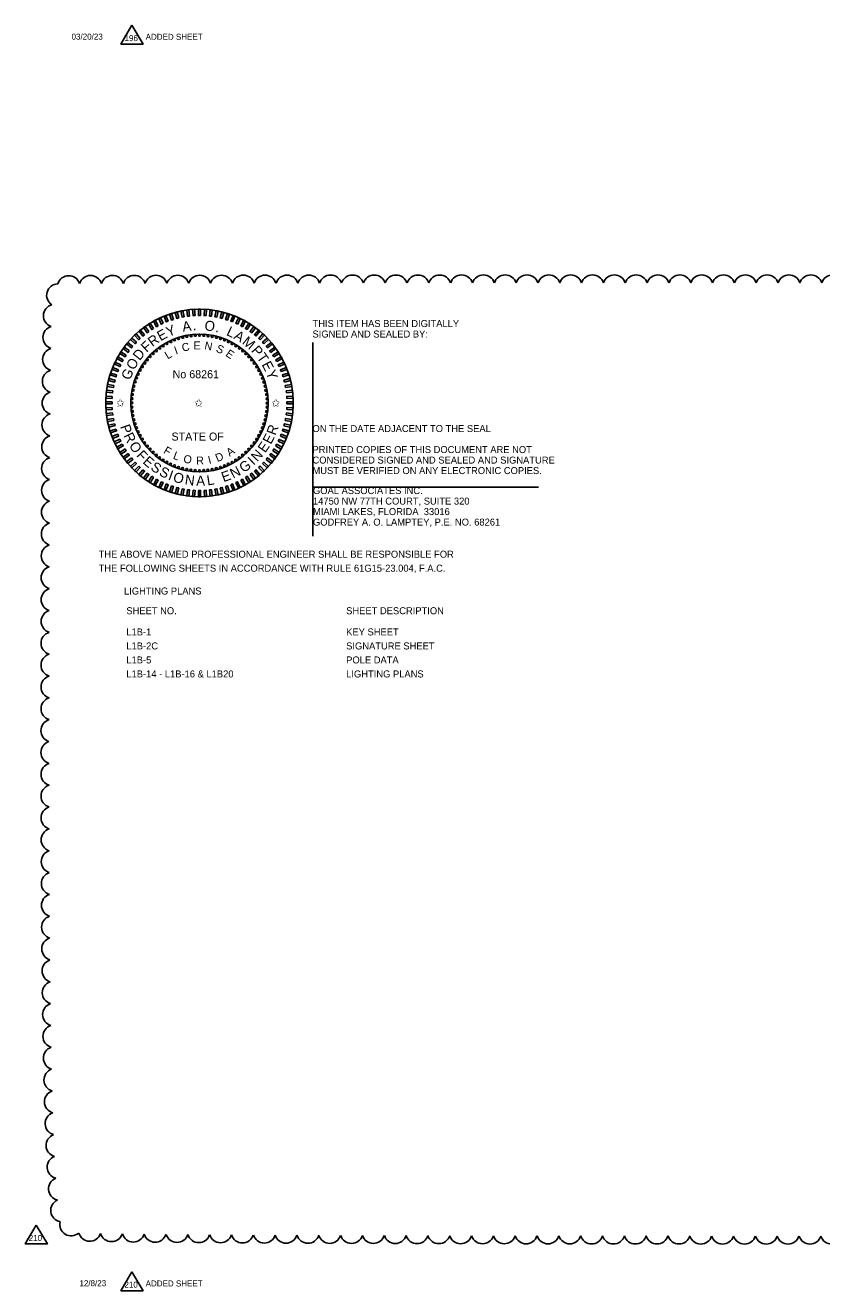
# Model space of a CAD drawing. Extents: x -811.2 to -755.6, y -2295.2 to -2235.1.
# Drawn here: x -811.23 to -803.27, y -2282.51 to -2269.86 of the extents above; entities that cross this region are included whole.
import ezdxf

# ---------------------------------------------------------------- set-up
doc = ezdxf.new("R2010")
doc.units = 0
for name, color, linetype in [('Cloud_dp', 7, 'Continuous'), ('Logo_dp', 7, 'Continuous'), ('NonPlottingEle_dp', 7, 'Continuous'), ('ScratchEle_dp', 7, 'Continuous'), ('TextMinor', 7, 'Continuous'), ('TextMisc', 7, 'Continuous'), ('TextNotes', 7, 'Continuous')]:
    doc.layers.add(name, color=color, linetype=linetype)

msp = doc.modelspace()

# ---------------------------------------------------------------- linework, layer by layer
at = {"layer": 'Cloud_dp'}
for points in [[(-810.168, -2269.863), (-810.276, -2270.051), (-810.055, -2270.051)], [(-811.125, -2281.857), (-811.233, -2282.045), (-811.012, -2282.045)], [(-810.168, -2282.324), (-810.276, -2282.512), (-810.055, -2282.512)]]:
    msp.add_lwpolyline(points, close=True, dxfattribs=at)
for centre, start, end in [((-810.798, -2272.48), 18.0566, 163.0566), ((-810.58, -2272.478), 17.7998, 162.7998), ((-810.362, -2272.477), 17.7187, 162.7187), ((-810.143, -2272.477), 17.6743, 162.6743), ((-809.925, -2272.476), 17.6451, 162.6451), ((-809.707, -2272.476), 17.624, 162.624), ((-809.488, -2272.475), 17.6079, 162.6079), ((-809.27, -2272.475), 17.5951, 162.5951), ((-809.052, -2272.474), 17.5845, 162.5845), ((-808.834, -2272.474), 17.5756, 162.5756), ((-808.615, -2272.474), 17.568, 162.568), ((-808.397, -2272.474), 17.5614, 162.5614), ((-808.179, -2272.473), 17.5556, 162.5556), ((-807.96, -2272.473), 17.5505, 162.5505), ((-807.742, -2272.473), 17.5459, 162.5459), ((-807.524, -2272.473), 17.5417, 162.5417), ((-807.305, -2272.473), 17.5379, 162.5379), ((-807.087, -2272.473), 17.5344, 162.5344), ((-806.869, -2272.472), 17.5313, 162.5313), ((-806.65, -2272.472), 17.5283, 162.5283), ((-806.432, -2272.472), 17.5256, 162.5256), ((-806.214, -2272.472), 17.5231, 162.5231), ((-805.995, -2272.472), 17.5207, 162.5207), ((-805.777, -2272.472), 17.5185, 162.5185), ((-805.559, -2272.472), 17.5164, 162.5164), ((-805.34, -2272.472), 17.5145, 162.5145), ((-805.122, -2272.472), 17.5126, 162.5126), ((-804.904, -2272.472), 17.5109, 162.5109), ((-804.685, -2272.472), 17.5092, 162.5092), ((-804.467, -2272.472), 17.5077, 162.5077), ((-804.249, -2272.472), 17.5062, 162.5062), ((-804.03, -2272.472), 17.5048, 162.5048), ((-803.812, -2272.472), 17.5034, 162.5034), ((-803.594, -2272.472), 17.5021, 162.5021), ((-803.375, -2272.472), 17.5009, 162.5009), ((-803.157, -2272.472), 17.5, 162.5), ((-810.905, -2272.561), 91.4771, 236.4771), ((-810.937, -2272.766), 105.908, 250.908), ((-810.942, -2272.984), 106.4168, 251.4168), ((-810.945, -2273.203), 106.6762, 251.6762), ((-810.948, -2273.421), 106.841, 251.841), ((-810.95, -2273.639), 106.9576, 251.9576), ((-810.952, -2273.857), 107.0457, 252.0457), ((-810.954, -2274.076), 107.1154, 252.1154), ((-810.955, -2274.294), 107.1722, 252.1722), ((-810.956, -2274.512), 107.2198, 252.2198), ((-810.957, -2274.73), 107.2603, 252.2603), ((-810.958, -2274.949), 107.2954, 252.2954), ((-810.959, -2275.167), 107.3262, 252.3262), ((-810.96, -2275.385), 107.3535, 252.3535), ((-810.96, -2275.604), 107.3779, 252.3779), ((-810.96, -2275.822), 107.3998, 252.3998), ((-810.961, -2276.04), 107.4198, 252.4198), ((-810.961, -2276.259), 107.438, 252.438), ((-810.961, -2276.477), 107.4547, 252.4547), ((-810.961, -2276.695), 107.4701, 252.4701), ((-810.962, -2276.914), 107.4843, 252.4843), ((-810.962, -2277.132), 107.499, 252.499), ((-810.961, -2277.35), 107.5356, 252.5356), ((-810.961, -2277.568), 107.5822, 252.5822), ((-810.961, -2277.787), 107.6325, 252.6325), ((-810.96, -2278.005), 107.6869, 252.6869), ((-810.959, -2278.223), 107.7461, 252.7461), ((-810.958, -2278.442), 107.8108, 252.8108), ((-810.957, -2278.66), 107.8818, 252.8818), ((-810.955, -2278.878), 107.9604, 252.9604), ((-810.954, -2279.096), 108.0479, 253.0479), ((-810.951, -2279.315), 108.1461, 253.1461), ((-810.949, -2279.533), 108.2576, 253.2576), ((-810.945, -2279.751), 108.3854, 253.3854), ((-810.942, -2279.969), 108.534, 253.534), ((-810.938, -2280.187), 108.7099, 253.7099), ((-810.932, -2280.406), 108.9225, 253.9225), ((-810.927, -2280.624), 109.1867, 254.1867), ((-810.92, -2280.842), 109.5275, 254.5275), ((-810.911, -2281.06), 109.9909, 254.9909), ((-810.9, -2281.277), 110.6749, 255.6749), ((-810.886, -2281.494), 111.8417, 256.8417), ((-810.864, -2281.71), 114.6718, 259.6718), ((-810.774, -2281.85), 166.2299, 311.2299), ((-810.588, -2281.904), 196.1072, 341.1072), ((-810.37, -2281.908), 196.5738, 341.5738), ((-810.152, -2281.912), 196.7877, 341.7877), ((-809.934, -2281.914), 196.9179, 341.9179), ((-809.715, -2281.916), 197.008, 342.008), ((-809.497, -2281.918), 197.075, 342.075), ((-809.279, -2281.919), 197.1274, 342.1274), ((-809.061, -2281.921), 197.1699, 342.1699), ((-808.842, -2281.922), 197.2052, 342.2052), ((-808.624, -2281.923), 197.2352, 342.2352), ((-808.406, -2281.924), 197.261, 342.261), ((-808.187, -2281.925), 197.2836, 342.2836), ((-807.969, -2281.926), 197.3036, 342.3036), ((-807.751, -2281.926), 197.3214, 342.3214), ((-807.532, -2281.927), 197.3374, 342.3374), ((-807.314, -2281.928), 197.3519, 342.3519), ((-807.096, -2281.928), 197.3651, 342.3651), ((-806.878, -2281.929), 197.3773, 342.3773), ((-806.659, -2281.929), 197.3884, 342.3884), ((-806.441, -2281.929), 197.3987, 342.3987), ((-806.223, -2281.93), 197.4083, 342.4083), ((-806.004, -2281.93), 197.4172, 342.4172), ((-805.786, -2281.93), 197.4256, 342.4256), ((-805.568, -2281.931), 197.4334, 342.4334), ((-805.349, -2281.931), 197.4407, 342.4407), ((-805.131, -2281.931), 197.4476, 342.4476), ((-804.913, -2281.931), 197.4542, 342.4542), ((-804.694, -2281.931), 197.4604, 342.4604), ((-804.476, -2281.932), 197.4662, 342.4662), ((-804.258, -2281.932), 197.4718, 342.4718), ((-804.039, -2281.932), 197.4771, 342.4771), ((-803.821, -2281.932), 197.4821, 342.4821), ((-803.603, -2281.932), 197.487, 342.487), ((-803.384, -2281.932), 197.4916, 342.4916), ((-803.166, -2281.932), 197.496, 342.496)]:
    msp.add_arc(centre, 0.114, start, end, dxfattribs=at)
at = {"layer": 'Logo_dp'}
for p, q in [((-809.5, -2274.576), (-809.5, -2274.513)), ((-809.49, -2274.576), (-809.49, -2274.513)), ((-809.48, -2274.576), (-809.48, -2274.513))]:
    msp.add_line(p, q, dxfattribs=at)
for points in [[(-809.903, -2272.866), (-809.92, -2272.876), (-809.951, -2272.821), (-809.933, -2272.812)], [(-809.853, -2272.842), (-809.872, -2272.851), (-809.898, -2272.794), (-809.88, -2272.785)], [(-809.803, -2272.821), (-809.822, -2272.828), (-809.845, -2272.77), (-809.826, -2272.763)], [(-809.751, -2272.803), (-809.77, -2272.809), (-809.789, -2272.75), (-809.77, -2272.743)], [(-809.698, -2272.788), (-809.717, -2272.793), (-809.733, -2272.733), (-809.713, -2272.727)], [(-809.644, -2272.777), (-809.664, -2272.78), (-809.676, -2272.719), (-809.656, -2272.715)], [(-809.59, -2272.769), (-809.61, -2272.771), (-809.618, -2272.709), (-809.598, -2272.707)], [(-809.535, -2272.764), (-809.555, -2272.765), (-809.559, -2272.703), (-809.539, -2272.702)], [(-809.48, -2272.763), (-809.5, -2272.763), (-809.5, -2272.701), (-809.48, -2272.701)], [(-809.425, -2272.765), (-809.445, -2272.764), (-809.441, -2272.702), (-809.421, -2272.703)], [(-809.37, -2272.771), (-809.39, -2272.769), (-809.383, -2272.707), (-809.363, -2272.709)], [(-809.316, -2272.78), (-809.336, -2272.777), (-809.324, -2272.715), (-809.304, -2272.719)], [(-809.263, -2272.793), (-809.282, -2272.788), (-809.267, -2272.728), (-809.247, -2272.733)], [(-809.21, -2272.809), (-809.229, -2272.803), (-809.21, -2272.743), (-809.191, -2272.75)], [(-809.159, -2272.828), (-809.177, -2272.821), (-809.154, -2272.763), (-809.136, -2272.77)], [(-809.108, -2272.851), (-809.127, -2272.842), (-809.1, -2272.786), (-809.082, -2272.794)], [(-809.06, -2272.876), (-809.077, -2272.866), (-809.047, -2272.812), (-809.03, -2272.821)], [(-810.082, -2272.993), (-810.096, -2273.007), (-810.139, -2272.962), (-810.124, -2272.948)], [(-810.04, -2272.957), (-810.056, -2272.97), (-810.095, -2272.922), (-810.08, -2272.909)], [(-809.996, -2272.924), (-810.013, -2272.936), (-810.049, -2272.885), (-810.033, -2272.874)], [(-809.95, -2272.894), (-809.967, -2272.905), (-810.001, -2272.852), (-809.984, -2272.841)], [(-809.013, -2272.905), (-809.03, -2272.894), (-808.996, -2272.841), (-808.979, -2272.852)], [(-808.968, -2272.936), (-808.984, -2272.924), (-808.947, -2272.874), (-808.931, -2272.886)], [(-808.925, -2272.97), (-808.94, -2272.957), (-808.9, -2272.909), (-808.885, -2272.922)], [(-808.884, -2273.007), (-808.898, -2272.993), (-808.856, -2272.948), (-808.841, -2272.962)], [(-810.158, -2273.072), (-810.171, -2273.088), (-810.219, -2273.048), (-810.206, -2273.033)], [(-810.121, -2273.032), (-810.135, -2273.046), (-810.18, -2273.004), (-810.167, -2272.989)], [(-808.845, -2273.046), (-808.859, -2273.032), (-808.814, -2272.989), (-808.8, -2273.004)], [(-808.809, -2273.088), (-808.822, -2273.073), (-808.774, -2273.033), (-808.761, -2273.048)], [(-810.252, -2273.208), (-810.262, -2273.225), (-810.316, -2273.195), (-810.307, -2273.177)], [(-810.223, -2273.161), (-810.234, -2273.178), (-810.287, -2273.144), (-810.276, -2273.127)], [(-810.192, -2273.115), (-810.204, -2273.132), (-810.254, -2273.095), (-810.243, -2273.079)], [(-808.776, -2273.132), (-808.788, -2273.116), (-808.738, -2273.079), (-808.726, -2273.095)], [(-808.746, -2273.178), (-808.757, -2273.161), (-808.704, -2273.127), (-808.693, -2273.144)], [(-808.718, -2273.225), (-808.728, -2273.208), (-808.673, -2273.178), (-808.664, -2273.195)], [(-810.3, -2273.306), (-810.307, -2273.325), (-810.365, -2273.302), (-810.358, -2273.283)], [(-810.278, -2273.256), (-810.286, -2273.275), (-810.343, -2273.248), (-810.334, -2273.23)], [(-808.694, -2273.275), (-808.703, -2273.256), (-808.646, -2273.23), (-808.638, -2273.248)], [(-808.673, -2273.325), (-808.68, -2273.307), (-808.622, -2273.284), (-808.615, -2273.302)], [(-810.348, -2273.464), (-810.352, -2273.484), (-810.413, -2273.472), (-810.409, -2273.452)], [(-810.335, -2273.411), (-810.34, -2273.43), (-810.401, -2273.415), (-810.396, -2273.395)], [(-810.319, -2273.358), (-810.325, -2273.377), (-810.385, -2273.358), (-810.379, -2273.339)], [(-808.655, -2273.377), (-808.661, -2273.358), (-808.602, -2273.339), (-808.595, -2273.358)], [(-808.64, -2273.43), (-808.645, -2273.411), (-808.585, -2273.395), (-808.58, -2273.415)], [(-808.629, -2273.484), (-808.632, -2273.464), (-808.571, -2273.453), (-808.567, -2273.472)], [(-810.363, -2273.573), (-810.364, -2273.593), (-810.426, -2273.589), (-810.425, -2273.569)], [(-810.357, -2273.518), (-810.36, -2273.538), (-810.421, -2273.53), (-810.419, -2273.51)], [(-808.621, -2273.538), (-808.623, -2273.518), (-808.561, -2273.511), (-808.559, -2273.531)], [(-808.616, -2273.593), (-808.617, -2273.573), (-808.555, -2273.569), (-808.554, -2273.589)], [(-810.365, -2273.628), (-810.365, -2273.648), (-810.428, -2273.648), (-810.428, -2273.628)], [(-810.364, -2273.683), (-810.363, -2273.703), (-810.425, -2273.707), (-810.426, -2273.687)], [(-808.617, -2273.703), (-808.616, -2273.683), (-808.554, -2273.687), (-808.555, -2273.707)], [(-808.615, -2273.648), (-808.615, -2273.628), (-808.553, -2273.628), (-808.553, -2273.648)], [(-810.36, -2273.738), (-810.357, -2273.758), (-810.419, -2273.765), (-810.421, -2273.745)], [(-810.352, -2273.792), (-810.348, -2273.812), (-810.409, -2273.824), (-810.413, -2273.804)], [(-808.632, -2273.812), (-808.629, -2273.792), (-808.567, -2273.804), (-808.571, -2273.824)], [(-808.623, -2273.758), (-808.621, -2273.738), (-808.559, -2273.746), (-808.561, -2273.766)], [(-810.34, -2273.846), (-810.335, -2273.865), (-810.396, -2273.881), (-810.401, -2273.861)], [(-810.325, -2273.899), (-810.319, -2273.918), (-810.379, -2273.937), (-810.385, -2273.918)], [(-810.307, -2273.951), (-810.3, -2273.969), (-810.358, -2273.992), (-810.366, -2273.974)], [(-808.68, -2273.97), (-808.673, -2273.951), (-808.615, -2273.974), (-808.622, -2273.993)], [(-808.661, -2273.918), (-808.655, -2273.899), (-808.595, -2273.918), (-808.602, -2273.937)], [(-808.645, -2273.866), (-808.64, -2273.846), (-808.58, -2273.861), (-808.585, -2273.881)], [(-810.286, -2274.001), (-810.278, -2274.02), (-810.334, -2274.046), (-810.343, -2274.028)], [(-810.262, -2274.051), (-810.252, -2274.068), (-810.307, -2274.098), (-810.317, -2274.081)], [(-808.728, -2274.069), (-808.719, -2274.051), (-808.664, -2274.081), (-808.674, -2274.099)], [(-808.703, -2274.02), (-808.694, -2274.002), (-808.638, -2274.028), (-808.646, -2274.046)], [(-810.234, -2274.098), (-810.224, -2274.115), (-810.276, -2274.149), (-810.287, -2274.132)], [(-810.204, -2274.144), (-810.192, -2274.16), (-810.243, -2274.197), (-810.255, -2274.181)], [(-810.171, -2274.188), (-810.158, -2274.204), (-810.206, -2274.243), (-810.219, -2274.228)], [(-808.822, -2274.204), (-808.81, -2274.188), (-808.761, -2274.228), (-808.774, -2274.243)], [(-808.788, -2274.161), (-808.776, -2274.144), (-808.726, -2274.181), (-808.738, -2274.197)], [(-808.757, -2274.116), (-808.746, -2274.098), (-808.693, -2274.132), (-808.704, -2274.149)], [(-810.135, -2274.23), (-810.121, -2274.244), (-810.167, -2274.287), (-810.18, -2274.272)], [(-810.097, -2274.269), (-810.082, -2274.283), (-810.125, -2274.328), (-810.139, -2274.314)], [(-810.056, -2274.306), (-810.04, -2274.319), (-810.08, -2274.367), (-810.096, -2274.354)], [(-810.013, -2274.34), (-809.996, -2274.352), (-810.033, -2274.402), (-810.049, -2274.39)], [(-808.984, -2274.352), (-808.968, -2274.34), (-808.931, -2274.391), (-808.947, -2274.402)], [(-808.94, -2274.319), (-808.925, -2274.306), (-808.885, -2274.354), (-808.9, -2274.367)], [(-808.899, -2274.283), (-808.884, -2274.269), (-808.841, -2274.315), (-808.856, -2274.328)], [(-808.859, -2274.244), (-808.845, -2274.23), (-808.8, -2274.272), (-808.814, -2274.287)], [(-809.968, -2274.371), (-809.951, -2274.382), (-809.984, -2274.435), (-810.001, -2274.424)], [(-809.921, -2274.4), (-809.903, -2274.41), (-809.933, -2274.464), (-809.951, -2274.455)], [(-809.872, -2274.425), (-809.854, -2274.434), (-809.88, -2274.491), (-809.898, -2274.482)], [(-809.822, -2274.448), (-809.803, -2274.455), (-809.826, -2274.513), (-809.845, -2274.506)], [(-809.77, -2274.467), (-809.751, -2274.473), (-809.77, -2274.533), (-809.79, -2274.526)], [(-809.229, -2274.473), (-809.21, -2274.467), (-809.191, -2274.527), (-809.21, -2274.533)], [(-809.177, -2274.455), (-809.159, -2274.448), (-809.136, -2274.506), (-809.154, -2274.513)], [(-809.127, -2274.434), (-809.109, -2274.426), (-809.082, -2274.482), (-809.1, -2274.491)], [(-809.077, -2274.41), (-809.06, -2274.4), (-809.03, -2274.455), (-809.047, -2274.464)], [(-809.03, -2274.382), (-809.013, -2274.371), (-808.979, -2274.424), (-808.996, -2274.435)], [(-809.718, -2274.483), (-809.698, -2274.488), (-809.714, -2274.549), (-809.733, -2274.544)], [(-809.664, -2274.496), (-809.644, -2274.499), (-809.656, -2274.561), (-809.676, -2274.557)], [(-809.61, -2274.505), (-809.59, -2274.507), (-809.598, -2274.569), (-809.618, -2274.567)], [(-809.555, -2274.511), (-809.535, -2274.512), (-809.539, -2274.574), (-809.559, -2274.573)], [(-809.5, -2274.513), (-809.48, -2274.513), (-809.48, -2274.576), (-809.5, -2274.576)], [(-809.445, -2274.512), (-809.425, -2274.511), (-809.421, -2274.573), (-809.441, -2274.574)], [(-809.391, -2274.507), (-809.371, -2274.505), (-809.363, -2274.567), (-809.383, -2274.569)], [(-809.336, -2274.499), (-809.316, -2274.496), (-809.305, -2274.557), (-809.324, -2274.561)], [(-809.282, -2274.488), (-809.263, -2274.483), (-809.247, -2274.544), (-809.267, -2274.549)]]:
    msp.add_lwpolyline(points, close=True, dxfattribs=at)
for centre in [(-809.853, -2273.066), (-809.816, -2273.044), (-809.778, -2273.025), (-809.739, -2273.008), (-809.699, -2272.994), (-809.658, -2272.982), (-809.617, -2272.972), (-809.574, -2272.966), (-809.532, -2272.962), (-809.49, -2272.961), (-809.447, -2272.962), (-809.405, -2272.966), (-809.363, -2272.973), (-809.321, -2272.982), (-809.28, -2272.994), (-809.24, -2273.008), (-809.201, -2273.025), (-809.163, -2273.045), (-809.127, -2273.066), (-810.012, -2273.206), (-809.984, -2273.174), (-809.953, -2273.144), (-809.922, -2273.116), (-809.888, -2273.09), (-809.091, -2273.09), (-809.058, -2273.116), (-809.026, -2273.145), (-808.996, -2273.175), (-808.968, -2273.207), (-810.084, -2273.311), (-810.062, -2273.275), (-810.038, -2273.239), (-808.942, -2273.24), (-808.918, -2273.276), (-808.896, -2273.312), (-810.134, -2273.428), (-810.12, -2273.388), (-810.103, -2273.349), (-808.877, -2273.35), (-808.86, -2273.389), (-808.846, -2273.429), (-810.162, -2273.553), (-810.155, -2273.511), (-810.146, -2273.469), (-808.834, -2273.47), (-808.825, -2273.512), (-808.818, -2273.554), (-810.168, -2273.637), (-810.166, -2273.595), (-810.166, -2273.68), (-808.814, -2273.596), (-808.814, -2273.681), (-808.813, -2273.639), (-810.162, -2273.722), (-810.156, -2273.764), (-810.146, -2273.806), (-808.834, -2273.807), (-808.825, -2273.766), (-808.818, -2273.724), (-810.135, -2273.847), (-810.12, -2273.887), (-810.103, -2273.926), (-810.084, -2273.964), (-808.897, -2273.965), (-808.877, -2273.927), (-808.86, -2273.888), (-808.846, -2273.848), (-810.062, -2274.001), (-810.039, -2274.036), (-810.012, -2274.069), (-808.968, -2274.07), (-808.942, -2274.037), (-808.918, -2274.002), (-809.984, -2274.101), (-809.954, -2274.132), (-809.922, -2274.16), (-809.889, -2274.186), (-809.854, -2274.21), (-809.128, -2274.21), (-809.092, -2274.186), (-809.059, -2274.16), (-809.027, -2274.132), (-808.997, -2274.102), (-809.817, -2274.231), (-809.779, -2274.251), (-809.74, -2274.268), (-809.7, -2274.282), (-809.659, -2274.294), (-809.618, -2274.303), (-809.576, -2274.31), (-809.533, -2274.314), (-809.49, -2274.316), (-809.448, -2274.314), (-809.406, -2274.31), (-809.364, -2274.304), (-809.322, -2274.294), (-809.281, -2274.283), (-809.241, -2274.268), (-809.202, -2274.251), (-809.164, -2274.232)]:
    msp.add_circle(centre, 0.01, dxfattribs=at)
at = {"layer": 'NonPlottingEle_dp'}
for radius in [0.938, 0.688]:
    msp.add_circle((-809.49, -2273.638), radius, dxfattribs=at)
at = {"layer": 'ScratchEle_dp'}
for p, q in [((-808.355, -2273.035), (-808.355, -2274.969)), ((-808.355, -2274.479), (-806.098, -2274.479))]:
    msp.add_line(p, q, dxfattribs=at)

# ---------------------------------------------------------------- texts
at = {"layer": 'Cloud_dp'}
for s, p in [('196', (-810.24, -2270.021)), ('210', (-811.198, -2282.015)), ('210', (-810.241, -2282.482))]:
    msp.add_text(s, height=0.06, rotation=0, dxfattribs=at).set_placement(p)
at = {"layer": 'Logo_dp'}
for s, height, rotation, p in [('A', 0.1, 8.8088, (-809.655, -2272.927)), ('O', 0.1, 352.1877, (-809.445, -2272.91)), ('E', 0.1, 28.1055, (-809.881, -2273.022)), ('Y', 0.1, 21.0633, (-809.802, -2272.979)), ('.', 0.1, 1.0418, (-809.558, -2272.912)), ('.', 0.1, 343.5268, (-809.336, -2272.925)), ('L', 0.1, 334.6727, (-809.228, -2272.957)), ('A', 0.1, 328.4096, (-809.155, -2272.99)), ('F', 0.1, 42.3772, (-810.02, -2273.137)), ('R', 0.1, 35.9269, (-809.961, -2273.081)), ('I', 0.08, 20.0117, (-809.726, -2273.154)), ('C', 0.08, 12.2025, (-809.658, -2273.126)), ('E', 0.08, 0.4186, (-809.55, -2273.103)), ('N', 0.08, 349.2914, (-809.445, -2273.101)), ('S', 0.08, 337.0221, (-809.332, -2273.123)), ('M', 0.1, 320.6426, (-809.071, -2273.041)), ('P', 0.1, 311.1966, (-808.978, -2273.118)), ('O', 0.1, 59.5178, (-810.145, -2273.316)), ('D', 0.1, 50.8569, (-810.089, -2273.221)), ('L', 0.08, 30.4021, (-809.809, -2273.204)), ('E', 0.08, 325.8663, (-809.236, -2273.163)), ('T', 0.1, 304.4563, (-808.921, -2273.182)), ('G', 0.1, 68.0518, (-810.185, -2273.416)), ('E', 0.1, 297.6315, (-808.871, -2273.253)), ('Y', 0.1, 290.5893, (-808.828, -2273.331)), ('P', 0.1, 289.4055, (-810.285, -2273.873)), ('R', 0.1, 296.1458, (-810.252, -2273.964)), ('E', 0.1, 62.4712, (-808.776, -2274.058)), ('R', 0.1, 69.5134, (-808.73, -2273.968)), ('O', 0.1, 303.9671, (-810.2, -2274.065)), ('F', 0.08, 328.7241, (-809.858, -2274.135)), ('A', 0.08, 34.4992, (-809.188, -2274.177)), ('E', 0.1, 55.4289, (-808.833, -2274.143)), ('F', 0.1, 312.628, (-810.128, -2274.167)), ('E', 0.1, 319.0783, (-810.064, -2274.235)), ('L', 0.08, 339.2916, (-809.761, -2274.194)), ('O', 0.08, 349.6821, (-809.656, -2274.233)), ('R', 0.08, 2.3398, (-809.522, -2274.255)), ('I', 0.08, 14.2037, (-809.394, -2274.249)), ('D', 0.08, 22.0128, (-809.312, -2274.23)), ('I', 0.1, 43.6456, (-808.95, -2274.266)), ('N', 0.1, 47.1788, (-808.912, -2274.232)), ('S', 0.1, 326.1206, (-809.987, -2274.301)), ('S', 0.1, 333.193, (-809.902, -2274.357)), ('I', 0.1, 340.2654, (-809.81, -2274.402)), ('O', 0.1, 343.7986, (-809.762, -2274.421)), ('E', 0.1, 19.8191, (-809.25, -2274.431)), ('N', 0.1, 26.8614, (-809.154, -2274.396)), ('G', 0.1, 35.1115, (-809.049, -2274.34)), ('N', 0.1, 352.4595, (-809.641, -2274.453)), ('A', 0.1, 0.7097, (-809.523, -2274.466)), ('L', 0.1, 8.4767, (-809.41, -2274.463))]:
    msp.add_text(s, height=height, rotation=rotation, dxfattribs=at).set_placement(p)
for s, p in [('No 68261', (-809.759, -2273.391)), ('✩', (-810.325, -2273.676)), ('✩', (-809.54, -2273.676)), ('✩', (-808.769, -2273.676)), ('STATE OF', (-809.77, -2274.014))]:
    msp.add_text(s, height=0.08, dxfattribs=at).set_placement(p)
at = {"layer": 'TextMinor'}
for s, p in [('03/20/23', (-810.77, -2270.006)), ('ADDED SHEET', (-810.029, -2270.008)), ('12/8/23', (-810.691, -2282.467)), ('ADDED SHEET', (-810.029, -2282.47))]:
    msp.add_text(s, height=0.06, dxfattribs=at).set_placement(p)
at = {"layer": 'TextMisc'}
for s, p in [('THIS ITEM HAS BEEN DIGITALLY', (-808.36, -2272.879)), ('SIGNED AND SEALED BY:', (-808.36, -2272.984)), ('ON THE DATE ADJACENT TO THE SEAL', (-808.36, -2273.929)), ('PRINTED COPIES OF THIS DOCUMENT ARE NOT ', (-808.36, -2274.139)), ('CONSIDERED SIGNED AND SEALED AND SIGNATURE ', (-808.36, -2274.244)), ('MUST BE VERIFIED ON ANY ELECTRONIC COPIES.', (-808.36, -2274.349)), ('GOAL ASSOCIATES INC.', (-808.355, -2274.549)), ('14750 NW 77TH COURT, SUITE 320', (-808.355, -2274.654)), ('MIAMI LAKES, FLORIDA  33016', (-808.355, -2274.759)), ('GODFREY A. O. LAMPTEY, P.E. NO. 68261', (-808.355, -2274.864)), ('THE ABOVE NAMED PROFESSIONAL ENGINEER SHALL BE RESPONSIBLE FOR ', (-810.499, -2275.185)), ('THE FOLLOWING SHEETS IN ACCORDANCE WITH RULE 61G15-23.004, F.A.C.', (-810.499, -2275.325)), ('LIGHTING PLANS', (-810.245, -2275.553))]:
    msp.add_text(s, height=0.07, dxfattribs=at).set_placement(p)
at = {"layer": 'TextNotes'}
for s, p in [('SHEET NO.', (-810.222, -2275.75)), ('SHEET DESCRIPTION', (-808.023, -2275.75)), ('L1B-1', (-810.222, -2275.962)), ('KEY SHEET', (-808.023, -2275.962)), ('L1B-2C', (-810.222, -2276.102)), ('SIGNATURE SHEET', (-808.023, -2276.102)), ('L1B-5', (-810.222, -2276.242)), ('POLE DATA', (-808.023, -2276.242)), ('L1B-14 - L1B-16 & L1B20', (-810.222, -2276.382)), ('LIGHTING PLANS', (-808.023, -2276.382))]:
    msp.add_text(s, height=0.07, dxfattribs=at).set_placement(p)

doc.saveas('drawing.dxf')
